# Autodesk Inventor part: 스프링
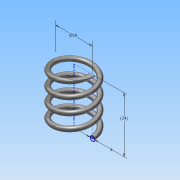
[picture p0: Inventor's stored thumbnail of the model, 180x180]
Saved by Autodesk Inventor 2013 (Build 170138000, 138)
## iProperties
Created: 2015-09
Part Number: 스프링
Material: 강철, 탄소
Document SubType Name: Modeling
Designer: Administrator
Density: 7.87 g/cm^3
Mass: 4.87902 g
Surface Area: 12.6234 cm^2
Volume: 0.619952 cm^3
Author: Administrator
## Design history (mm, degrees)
sketch "스케치1"
  geometry: L1 (0, 0)-(8, 0); L2 (8, 0)-(8, 24); L3 (8, 24)-(0, 24); L4 (0, 24)-(0, 0); C1 r 1 at (8, 0)
  constraints: 8 end point, 2 parallel, 1 centre point, 1 coincident, 1 horizontal, 1 perpendicular
  dimensions: "d0" = 16 diameter of L2 L4; "d2" = 24 distance of L1.end L2.end (derived); "d3" = 2 diameter of C1
feature "코일1" sketch "스케치1" pitch "d4" = 10; turns "d6" = 4; dims "d5" = 24 (= d2), "d7" = 0, angle "d8" = 90 deg, angle "d9" = 90 deg, "d10" = 0, "d11" = 0
sketch "스케치2"
  geometry: L1 (-9, 0)-(-7, 0) reference; 1 further point
  constraints: 1 horizontal alignment
extrude "돌출1" cut sketch "스케치2" distance "d12" = 10; taper "d13" = 0 deg
node "작업 평면1"
sketch "스케치3"
  geometry: L1 (2, 0)-(0, 0) reference; 1 further point
  constraints: 1 horizontal alignment
extrude "돌출2" cut sketch "스케치3" distance "d14" = 10; taper "d15" = 0 deg
node "솔리드1"
node "절단 모서리 투영1"
node "절단 모서리 투영2"
